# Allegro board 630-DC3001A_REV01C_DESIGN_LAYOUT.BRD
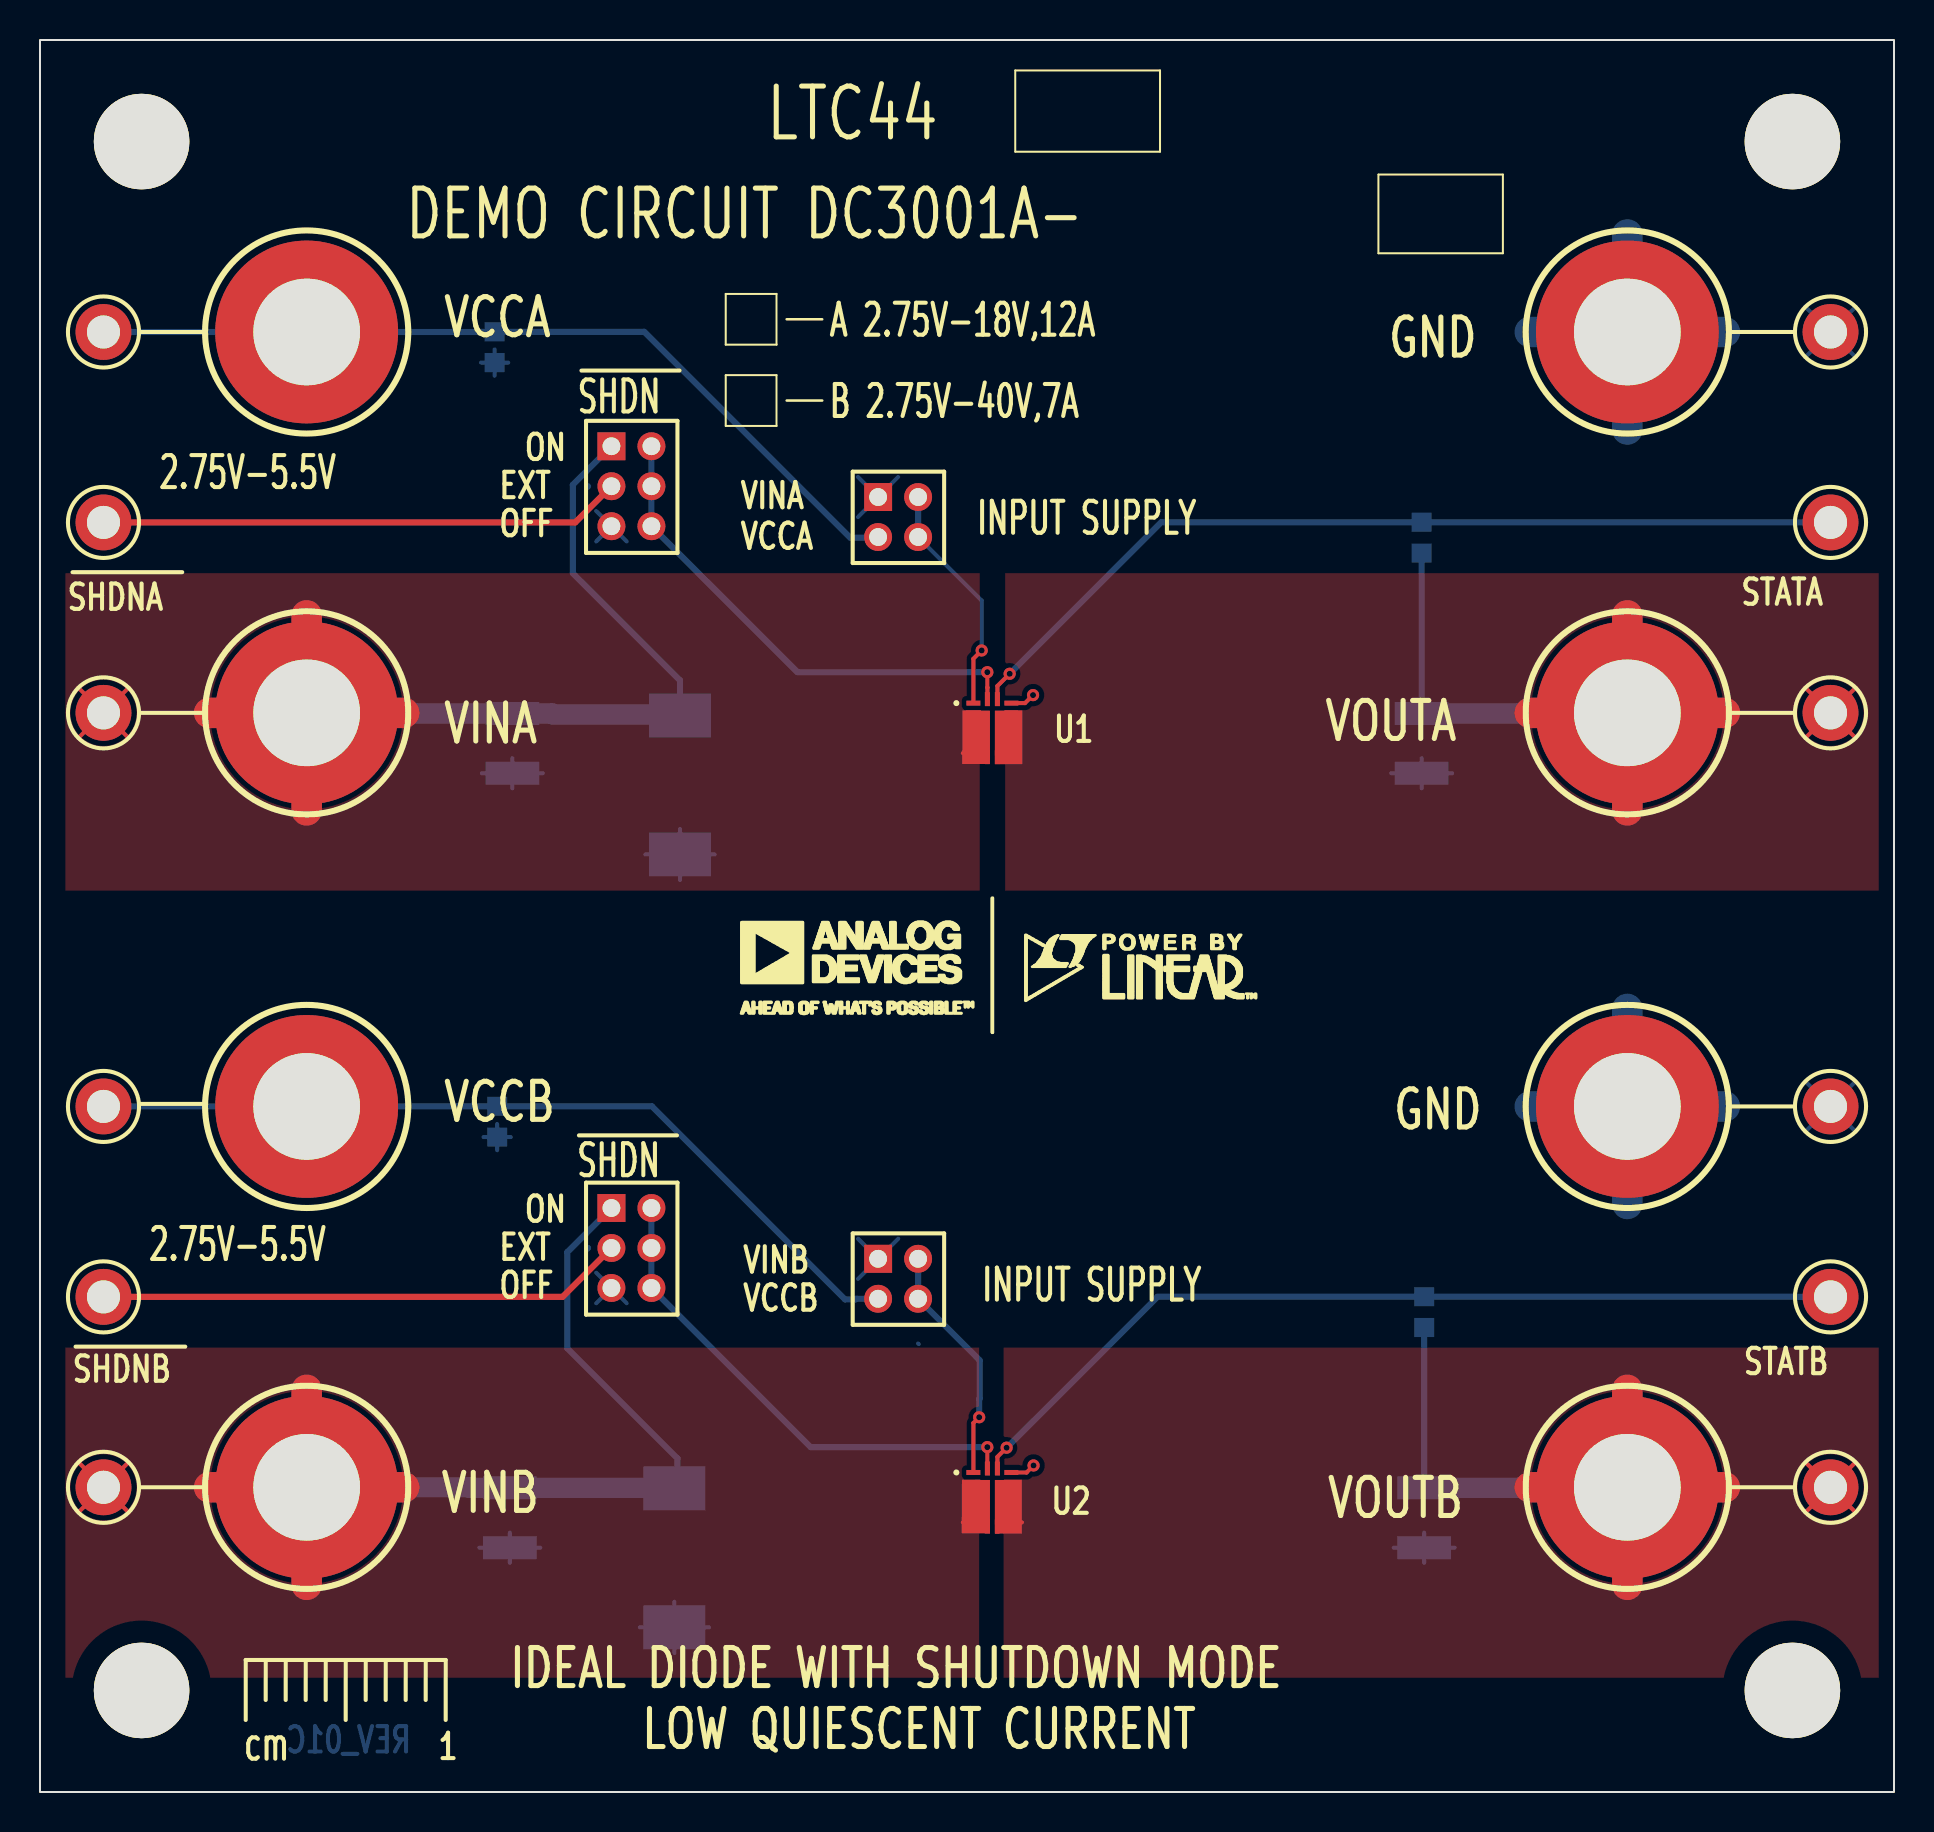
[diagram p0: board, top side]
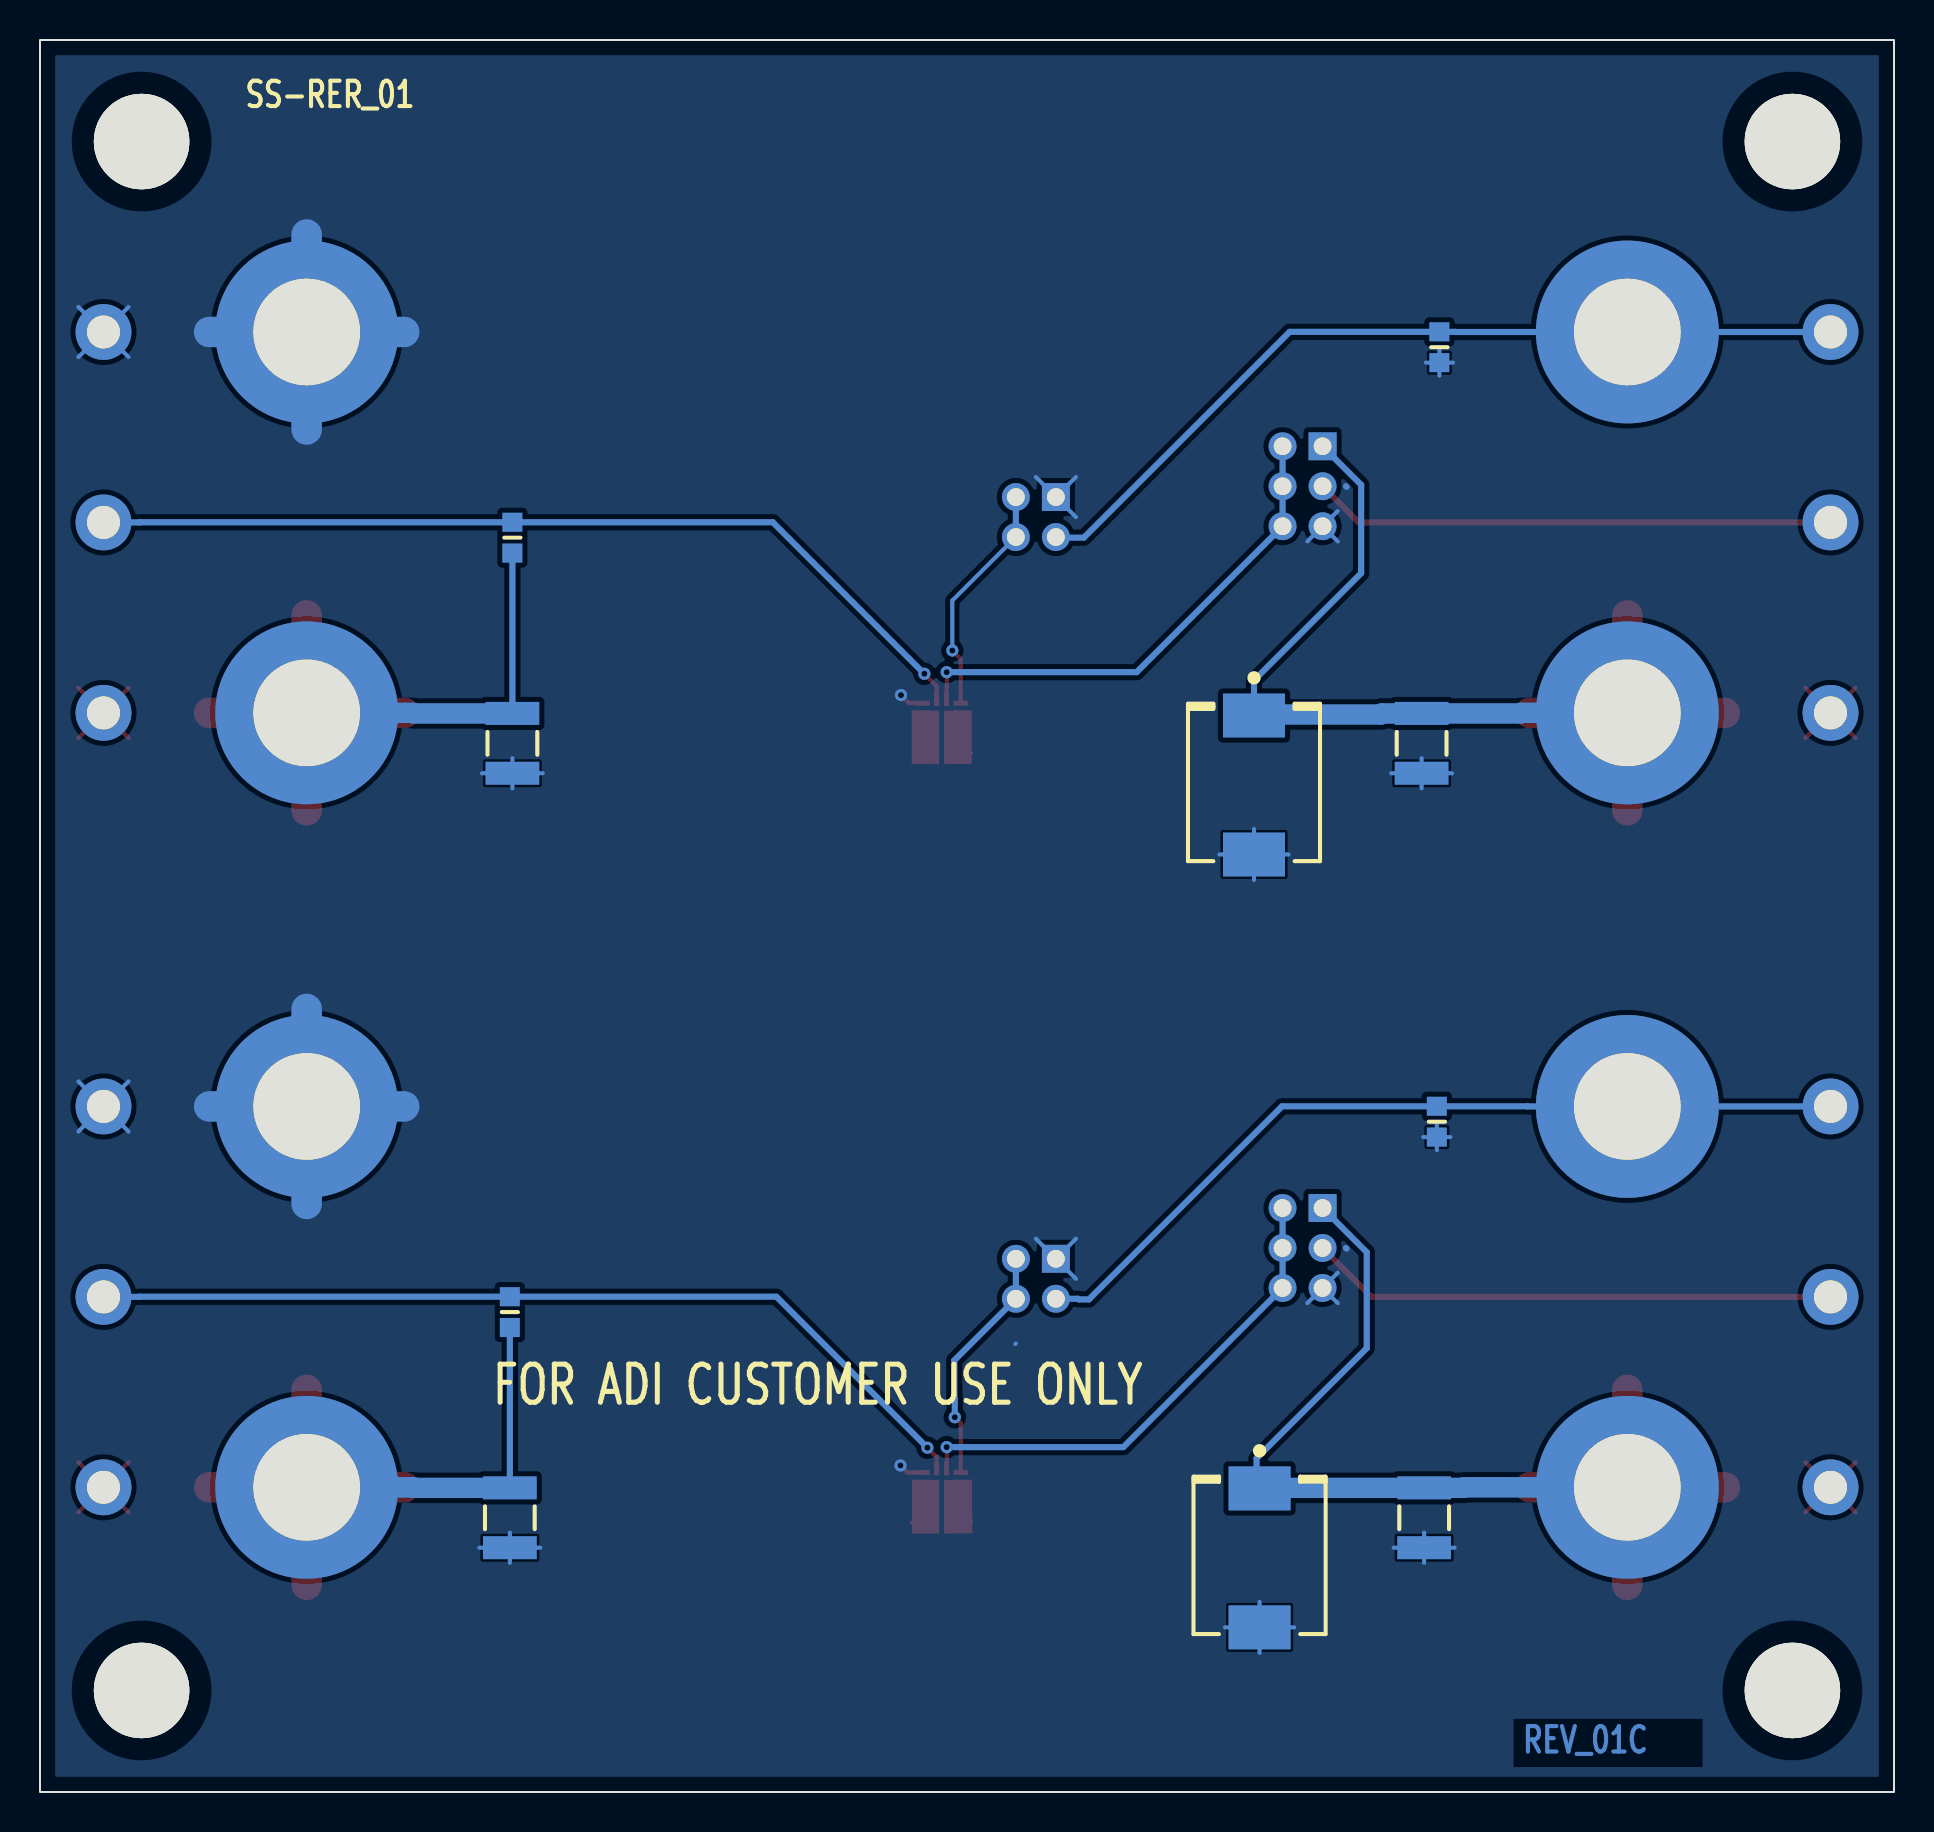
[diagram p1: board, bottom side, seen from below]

Outline 92.71 x 87.63 mm; copper layers: TOP, BOTTOM. Coordinates in mm from the lower left corner of the outline.
Outline path: rectangle 0,0 92.71,87.63

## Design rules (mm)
constraint set DEFAULT: min track width 0.203
net group GND_SIGNAL: nets N04054 N16606798 N16619254 N16619432

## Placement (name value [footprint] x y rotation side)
C1  OPT  [CC1210N]  69.09 52.45 270 bottom
C2  OPT  [CC1210N]  23.62 52.45 270 bottom
C3  OPT  [CC0603N]  22.73 72.26 270 bottom
C4  OPT  [CC1210N]  69.22 13.72 270 bottom
C5  OPT  [CC1210N]  23.5 13.72 270 bottom
C6  OPT  [CC0603N]  22.86 33.53 270 bottom
D1  SMCJ60A  [SMC-N]  32 50.37 270 bottom
D2  SMCJ60A  [SMC-N]  31.72 11.71 270 bottom
E1  TEST POINT  [MILLMAX2308-2]  3.17 63.5 0 top
E2  BANANA JACK  [KEY-575-4]  13.34 73.03 0 top
E3  TEST POINT  [MILLMAX2308-2]  3.17 73.03 0 top
E4  TEST POINT  [MILLMAX2308-2]  3.17 53.98 0 top
E5  BANANA JACK  [KEY-575-4]  13.34 53.98 0 top
E6  TEST POINT  [MILLMAX2308-2]  3.17 24.77 0 top
E7  BANANA JACK  [KEY-575-4]  13.34 34.29 0 top
E8  TEST POINT  [MILLMAX2308-2]  3.17 34.29 0 top
E9  BANANA JACK  [KEY-575-4]  13.34 15.24 0 top
E10  TEST POINT  [MILLMAX2308-2]  3.17 15.24 0 top
E11  BANANA JACK  [KEY-575-4]  79.38 73.03 0 top
E12  TEST POINT  [MILLMAX2308-2]  89.53 63.5 0 top
E13  TEST POINT  [MILLMAX2308-2]  89.53 73.03 0 top
E14  BANANA JACK  [KEY-575-4]  79.38 53.98 0 top
E15  TEST POINT  [MILLMAX2308-2]  89.53 53.98 0 top
E16  BANANA JACK  [KEY-575-4]  79.38 34.29 0 top
E17  TEST POINT  [MILLMAX2308-2]  89.53 24.77 0 top
E18  BANANA JACK  [KEY-575-4]  79.38 15.24 0 top
E19  TEST POINT  [MILLMAX2308-2]  89.53 34.29 0 top
E20  TEST POINT  [MILLMAX2308-2]  89.53 15.24 0 top
JP1  HDR.  [HD2X3-079]  28.57 67.31 0 top
JP2  HDR  [HD2X2-079]  41.91 64.77 0 top
JP3  HDR.  [HD2X3-079]  28.57 29.21 0 top
JP4  HDR  [HD2X2-079]  41.91 26.67 0 top
MP1  STANDOFF  [KEYSTONE_8833]  87.63 82.55 0 top
MP2  STANDOFF  [KEYSTONE_8833]  87.63 5.08 0 top
MP3  STANDOFF  [KEYSTONE_8833]  5.08 82.55 0 top
MP4  STANDOFF  [KEYSTONE_8833]  5.08 5.08 0 top
NOREF  -  []  0 0 90 top
NOREF#2  -  []  0 87.63 0 top
NOREF#3  -  []  248.92 114.94 0 top
NOREF#4  -  []  -314.07 -134.75 0 top
NOREF#5  -  []  249.56 179.71 0 top
NOREF#6  -  []  -382.14 -201.8 0 top
NOREF#7  -  []  346.84 -132.21 0 top
NOREF#8  -  []  502.29 152.4 0 top
NOREF#9  -  []  102.87 35.56 0 top
NOREF#10  -  []  -83.69 -186.82 0 top
NOREF#11  -  []  10.29 6.6 0 top
NOREF#12  -  []  97.92 54.86 0 top
NOREF#13  -  []  248.92 77.47 0 top
R1  100k  [CR0603N]  69.09 62.74 270 bottom
R2  100k  [CR0603N]  69.22 24 270 bottom
U1  LTC4450HUB  [LTC-LQFN-16-1683]  47.62 53.21 0 top
U2  LTC4450HUB  [LTC-LQFN-16-1683]  47.62 14.73 0 top

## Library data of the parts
C1-C6 = CAP
D1 D2 = DIODE_TVS_B_ALT
E1 E3 E4 E6 E8 E10 E12 E13 E15 E17 E19 E20 = TEST_POINT_.156_MILL-MAX_2308
E2 E5 E7 E9 E11 E14 E16 E18 = BANANA_KEYSTONE-575-4
JP1 JP3 = HEADER_2X3_.079
JP2 JP4 = HEADER_2X2_.079
MP1-MP4 = MP-PINNED_ALT1
R1 R2 = RES
U1 U2 = LTC4450_51-LQFN

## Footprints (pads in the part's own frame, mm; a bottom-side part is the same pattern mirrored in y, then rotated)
CC0603N
  rect 0.955x1 smd: 1(-0.77,0) 2(0.77,0)
CC1210N
  rect 1.15x2.69 smd: 1(-1.496,0) 2(1.496,0)
CR0603N
  rect 0.955x1 smd: 1(-0.77,0) 2(0.77,0)
HD2X2-079
  rect 1.397x1.397 hole 0.889: 1(0,0)
  round 1.397 hole 0.889: 2(2,0) 3(0,-2) 4(2,-2)
HD2X3-079
  rect 1.397x1.397 hole 0.889: 1(0,0)
  round 1.397 hole 0.889: 2(2,0) 3(0,-2) 4(2,-2) 5(0,-4) 6(2,-4)
KEY-575-4
  round 9.144 hole 5.334: 1(0,0)
KEYSTONE_8833
  round 4.775 hole 4.775 unplated: (0,0)
LTC-LQFN-16-1683
  rect 0.7x0.25 smd: 1(-0.95,1.25) 2(-0.95,0.75) 3(-0.95,0.25) 4(-0.95,-0.25) 5(-0.95,-0.75) 6(-0.95,-1.25) 9(0.95,-1.25) 10(0.95,-0.75) 11(0.95,-0.25) 12(0.95,0.25) 13(0.95,0.75) 14(0.95,1.25)
  rect 0.25x0.7 smd: 7(-0.25,-1.45) 8(0.25,-1.45) 15(0.25,1.45) 16(-0.25,1.45)
MILLMAX2308-2
  round 2.794 hole 1.651: 1(0,0)
SMC-N
  rect 2.2x3.1 smd: 1(-3.475,0) 2(3.475,0)

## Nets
GND_SIGNAL: C1.2 C2.2 C3.2 C4.2 C5.2 C6.2 D1.2 D2.2 E11.1 E13.1(A) E16.1 E19.1(A) JP1.5 JP2.1 JP3.5 JP4.1 U1.14 U2.14
VIN_A: C2.1 D1.1(C) E4.1(A) E5.1 JP1.1 U1.2 U1.3 U1.4 U1.5 U1.6 U1.7
VIN_B: C5.1 D2.1(C) E9.1 E10.1(A) JP3.1 U2.2 U2.3 U2.4 U2.5 U2.6 U2.7
VOUT_A: C1.1 E14.1 E15.1(A) R1.2 U1.8 U1.9 U1.10 U1.11 U1.12 U1.13
VOUT_B: C4.1 E18.1 E20.1(A) R2.2 U2.8 U2.9 U2.10 U2.11 U2.12 U2.13
N04054: C3.1 E2.1 E3.1(A) JP2.3
N16606798: E12.1(A) R1.1 U1.15
N16608025: JP1.2 JP1.4 JP1.6 U1.16
N16614720: E1.1(A) JP1.3
N16616083: JP2.2 JP2.4 U1.1(VCC)
N16619238: JP3.2 JP3.4 JP3.6 U2.16
N16619254: E17.1(A) R2.1 U2.15
N16619282: E6.1(A) JP3.3
N16619358: JP4.2 JP4.4 U2.1(VCC)
N16619432: C6.1 E7.1 E8.1(A) JP4.3

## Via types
v1: diameter 0.61, hole 0.305, TOP to BOTTOM, 8 vias

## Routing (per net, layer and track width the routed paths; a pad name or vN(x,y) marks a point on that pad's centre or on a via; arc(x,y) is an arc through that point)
GND_SIGNAL: length 106.4
  TOP w0.203: v1(49.68,16.33) 49.33,15.98 U2.14 ; v1(49.66,54.86) 49.26,54.46 U1.14
  BOTTOM w0.203: 67.56,50.95 C1.2 ; C1.2 69.09,51.71 ; C1.2 69.09,50.2 ; C1.2 70.61,50.95 ; 67.69,12.22 C4.2 ; C4.2 69.22,12.97 ; C4.2 70.74,12.22 ; C4.2 69.22,11.47 ; C6.2 23.54,32.76 ; C6.2 22.86,32.1 ; C6.2 22.86,33.41 ; C6.2 22.18,32.76 ; JP3.5 29.34,24.45 ; JP3.5 27.81,24.45 ; JP3.5 27.81,25.97 ; C3.2 23.41,71.49 ; C3.2 22.05,71.49 ; C3.2 22.73,70.84 ; C3.2 22.73,72.15 ; D2.2 33.45,8.23 ; D2.2 31.72,9.51 ; D2.2 30,8.23 ; D2.2 31.72,6.96 ; 88.28,35.54 E19.1 ; E19.1 90.79,33.04 ; E19.1 90.79,35.54 ; E19.1 88.28,33.04 ; 43.91,22.43 43.94,22.4 ; 27.81,64.07 JP1.5 ; JP1.5 29.34,62.55 ; JP1.5 27.81,62.55 ; D1.2 33.73,46.89 ; D1.2 30.28,46.89 ; D1.2 32,45.61 ; D1.2 32,48.17 ; JP2.1 42.91,65.77 ; JP2.1 40.91,63.77 ; JP2.1 40.91,65.77 ; C5.2 23.5,12.97 ; C5.2 21.97,12.22 ; C5.2 23.5,11.47 ; C5.2 25.02,12.22 ; C2.2 25.15,50.95 ; C2.2 23.62,50.2 ; C2.2 23.62,51.71 ; C2.2 22.1,50.95 ; 88.28,74.28 E13.1 ; E13.1 90.79,74.28 ; E13.1 88.28,71.77 ; E13.1 90.79,71.77 ; JP4.1 42.91,27.67 ; JP4.1 40.91,27.67 ; JP4.1 40.91,25.67
  BOTTOM w0.305: 27.41,27.21 27.37,27.18 ; 27.41,65.31 27.37,65.28
  BOTTOM w1.524: E11.1 84.25,73.03 ; E11.1 79.38,77.9 ; E11.1 79.38,68.15 ; E11.1 74.5,73.03 ; E16.1 84.25,34.29 ; E16.1 74.5,34.29 ; E16.1 79.38,29.41 ; E16.1 79.38,39.17
VIN_A: length 62.6
  TOP w0.203: 46.15,51.96 U1.6 46.68,51.66 ; 1.92,55.23 E4.1 ; E4.1 4.43,52.72 ; E4.1 1.92,52.72 ; E4.1 4.43,55.23
  TOP w1.524: 8.46,53.98 E5.1 ; E5.1 18.21,53.98 ; E5.1 13.34,58.85 ; E5.1 13.34,49.1
  BOTTOM w0.203: D1.1 32,53.89
  BOTTOM w0.305: 32,53.89 32,55.6 26.64,60.96 26.64,65.38 JP1.1
  BOTTOM w1.016: E5.1 18.67,53.98 18.67,53.95 C2.1 25.6,53.95 25.66,53.89 32,53.89
VIN_B: length 63.2
  TOP w0.203: 1.92,13.99 E10.1 ; E10.1 1.92,16.49 ; E10.1 4.43,13.99 ; E10.1 4.43,16.49 ; 46.68,13.18 U2.6 46.15,13.48
  TOP w1.524: 8.46,15.24 E9.1 ; E9.1 13.34,10.36 ; E9.1 13.34,20.12 ; E9.1 18.21,15.24
  BOTTOM w0.203: 31.6,15.21 31.62,15.18 D2.1
  BOTTOM w0.305: JP3.1 26.37,27 26.37,22.2 31.88,16.69 31.88,15.34 D2.1
  BOTTOM w1.016: E9.1 21.51,15.24 21.51,15.21 C5.1 31.6,15.21
VOUT_A: length 44.9
  TOP w0.203: E15.1 90.79,55.23 ; E15.1 90.79,52.72 ; E15.1 88.28,52.72 ; E15.1 88.28,55.23
  TOP w1.524: 79.38,49.1 E14.1 ; E14.1 74.5,53.98 ; E14.1 84.25,53.98 ; E14.1 79.38,58.85
  BOTTOM w0.305: C1.1 R1.2
  BOTTOM w1.016: C1.1 74.04,53.95 74.04,53.98 E14.1
VOUT_B: length 45.6
  TOP w0.203: 49.1,13.48 U2.9 48.57,13.18 ; 88.28,13.99 E20.1 ; E20.1 90.79,16.49 ; E20.1 88.28,16.49 ; E20.1 90.79,13.99
  TOP w1.524: E18.1 79.38,20.12 ; E18.1 74.5,15.24 ; E18.1 84.25,15.24 ; E18.1 79.38,10.36
  BOTTOM w0.305: C4.1 R2.2
  BOTTOM w1.016: E18.1 74.04,15.24 74.04,15.21 C4.1
N04054: length 43
  BOTTOM w0.305: JP2.3 41.88,62.74 40.51,62.74 30.22,73.03 C3.1 21.95,73.03 21.95,73.03 E2.1 E3.1
N16606798: length 45.7
  TOP w0.203: U1.15 47.87,55.32 v1(48.49,55.93)
  BOTTOM w0.305: E12.1 87.73,63.5 87.73,63.51 R1.1 56.07,63.51 v1(48.49,55.93)
N16608025: length 25.2
  TOP w0.203: U1.16 47.38,55.24 47.37,55.25 v1(47.37,56.01)
  BOTTOM w0.305: v1(47.37,56.01) 37.87,56.01 JP1.6 JP1.4 JP1.2
N16614720: length 26.1
  TOP w0.305: E1.1 26.76,63.5 JP1.3
N16616083: length 11.8
  TOP w0.203: v1(47.09,57.1) 46.68,56.68 U1.1
  BOTTOM w0.203: JP2.4 47.09,59.59 v1(47.09,57.1)
  BOTTOM w0.305: JP2.2 JP2.4
N16619238: length 25.2
  TOP w0.203: U2.16 47.37,16.19 v1(47.37,17.25)
  BOTTOM w0.305: JP3.2 JP3.4 JP3.6 38.54,17.25 v1(47.37,17.25)
N16619254: length 45.6
  TOP w0.203: U2.15 47.87,16.76 v1(48.34,17.22)
  BOTTOM w0.305: E17.1 87.73,24.77 87.73,24.77 R2.1 55.89,24.77 v1(48.34,17.22)
N16619282: length 26.4
  TOP w0.305: JP3.3 26.13,24.77 E6.1
N16619358: length 12.1
  TOP w0.203: U2.1 46.68,18.46 v1(46.96,18.75)
  BOTTOM w0.305: JP4.2 JP4.4 46.99,21.59 46.99,19.68 46.96,19.66 v1(46.96,18.75)
N16619432: length 42.8
  BOTTOM w0.305: E8.1 E7.1 18.31,34.29 18.32,34.3 C6.1 30.6,34.3 40.26,24.64 40.77,24.64 40.81,24.67 JP4.3

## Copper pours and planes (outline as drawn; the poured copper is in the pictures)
GND_SIGNAL on BOTTOM: 0.76,86.87 91.95,86.87 91.95,0.76 0.76,0.76 ; 6 cut-outs
VIN_A on TOP (solid shape): 47.5,51.84 46.78,51.84 46.78,54.09 47.5,54.09
VIN_A on TOP (solid shape): 47.04,52.15 47.32,52.15 47.5,52.14 47.49,51.42 47.31,51.42 46.12,51.42 46.13,54.1 47.04,54.1
VIN_A on TOP: 1.27,60.96 1.27,45.09 46.99,45.09 46.99,60.96
VIN_B on TOP (solid shape): 47.5,13.36 46.78,13.36 46.78,15.61 47.5,15.61
VIN_B on TOP (solid shape): 47.02,13.67 47.29,13.67 47.5,13.66 47.5,12.94 47.29,12.94 46.09,12.94 46.1,15.62 47.02,15.62
VIN_B on TOP: 1.27,22.23 1.27,5.71 46.96,5.71 46.96,22.23
VOUT_A on TOP (solid shape): 48.47,51.84 47.75,51.84 47.75,54.09 48.47,54.09
VOUT_A on TOP (solid shape): 49.12,51.41 47.75,51.41 47.75,52.12 48.23,52.12 48.23,54.1 49.12,54.1
VOUT_A on TOP: 48.26,60.96 91.95,60.96 91.95,45.09 48.26,45.09
VOUT_B on TOP (solid shape): 48.47,13.36 47.75,13.36 47.75,15.61 48.47,15.61
VOUT_B on TOP (solid shape): 49.1,12.93 47.75,12.93 47.75,13.64 48.21,13.64 48.21,15.62 49.1,15.62
VOUT_B on TOP: 48.18,22.23 91.95,22.23 91.95,5.71 48.18,5.71

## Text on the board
BOTTOM: REV_01C | BOTTOM- LAYER2
Board Geometry/Soldermask Bottom: BOTTOM SOLDERMASK
Package Geometry/Pastemask Bottom: BOTTOM PASTEMASK
Ref Des/Silkscreen Bottom: SS-RER_01 | FOR ADI CUSTOMER USE ONLY | BOTTOM SILKSCREEN
User.Comments: M.HAWKINS | M.SINGH | 01B | SILKSCREEN EDITED | 11/30/20 | AARON.S | ASSEMBLY DRAWING, TOP | DC3001A | 705-DC3001A | ASSEMBLY DRAWING, BOTTOM
TOP: TOP-LAYER1
Board Geometry/Soldermask Top: TOP SOLDERMASK
Package Geometry/Pastemask Top: TOP PASTEMASK
Ref Des/Silkscreen Top: SHDNA | SHDNB | EXT | OFF | ON | VINA | VCCA | VINB | VCCB | STATA | STATB | 2.75V-5.5V | SHDN | A 2.75V-18V,12A | B 2.75V-40V,7A | INPUT SUPPLY | IDEAL DIODE WITH SHUTDOWN MODE | LOW QUIESCENT CURRENT | VOUTA | VOUTB | GND | DEMO CIRCUIT DC3001A- | TOP SILKSCREEN | LTC44
XSECTION_CHART: *  SURFACE - 0 MIL(+0/-0) | * SOLDERMASK_TOP MASK - 1.5 MIL(+0/-0) | * ENIG_TOP MASK - 0.18 MIL(+0/-0) | L1 TOP CONDUCTOR - 2.8 MIL(+0/-0) | *  DIELECTRIC - 54 MIL(+0/-0) | L2 BOTTOM CONDUCTOR - 2.8 MIL(+0/-0) | * ENIG_BOTTOM MASK - 0.18 MIL(+0/-0) | * SOLDERMASK_BOTTOM MASK - 1.5 MIL(+0/-0) | STACKUP TABLE | Unit = Mils | DESIGN CROSS SECTION CHART | ___________________________ | TOTAL THICKNESS 62.96 MIL | # | 1 | 2 | NAME | SOLDERMASK_TOP | ENIG_TOP | TOP | BOTTOM | ENIG_BOTTOM | SOLDERMASK_BOTTOM | TYPE | SURFACE | MASK | CONDUCTOR | DIELECTRIC | MATERIAL | AIR | PHOTOIMAGABLE_ACRYLIC | ENIG | COPPER | FR-4 | TOTAL THICKNESS | THICKNESS | 0 | 1.5 | 0.18 | 2.8 | 54 | 62.96 | TOLERANCE | +0/-0
DIMENSION: 10/22/19 | DRILL & FABRICATION DRAWING | 01B | 615-DC3001A | 1 OF 1
DEVICE_TYPE_TOP: FIGURE | SIZE | 12.0 | 35.0 | 65.0 | 210.0 | 188.0 | PLATED | NON-PLATED | FINISHED HOLES IN MILS | ALL UNITS ARE IN MILS | QTY | 8 | 20 | 12 | 4 | TOLERANCE/NOTES
